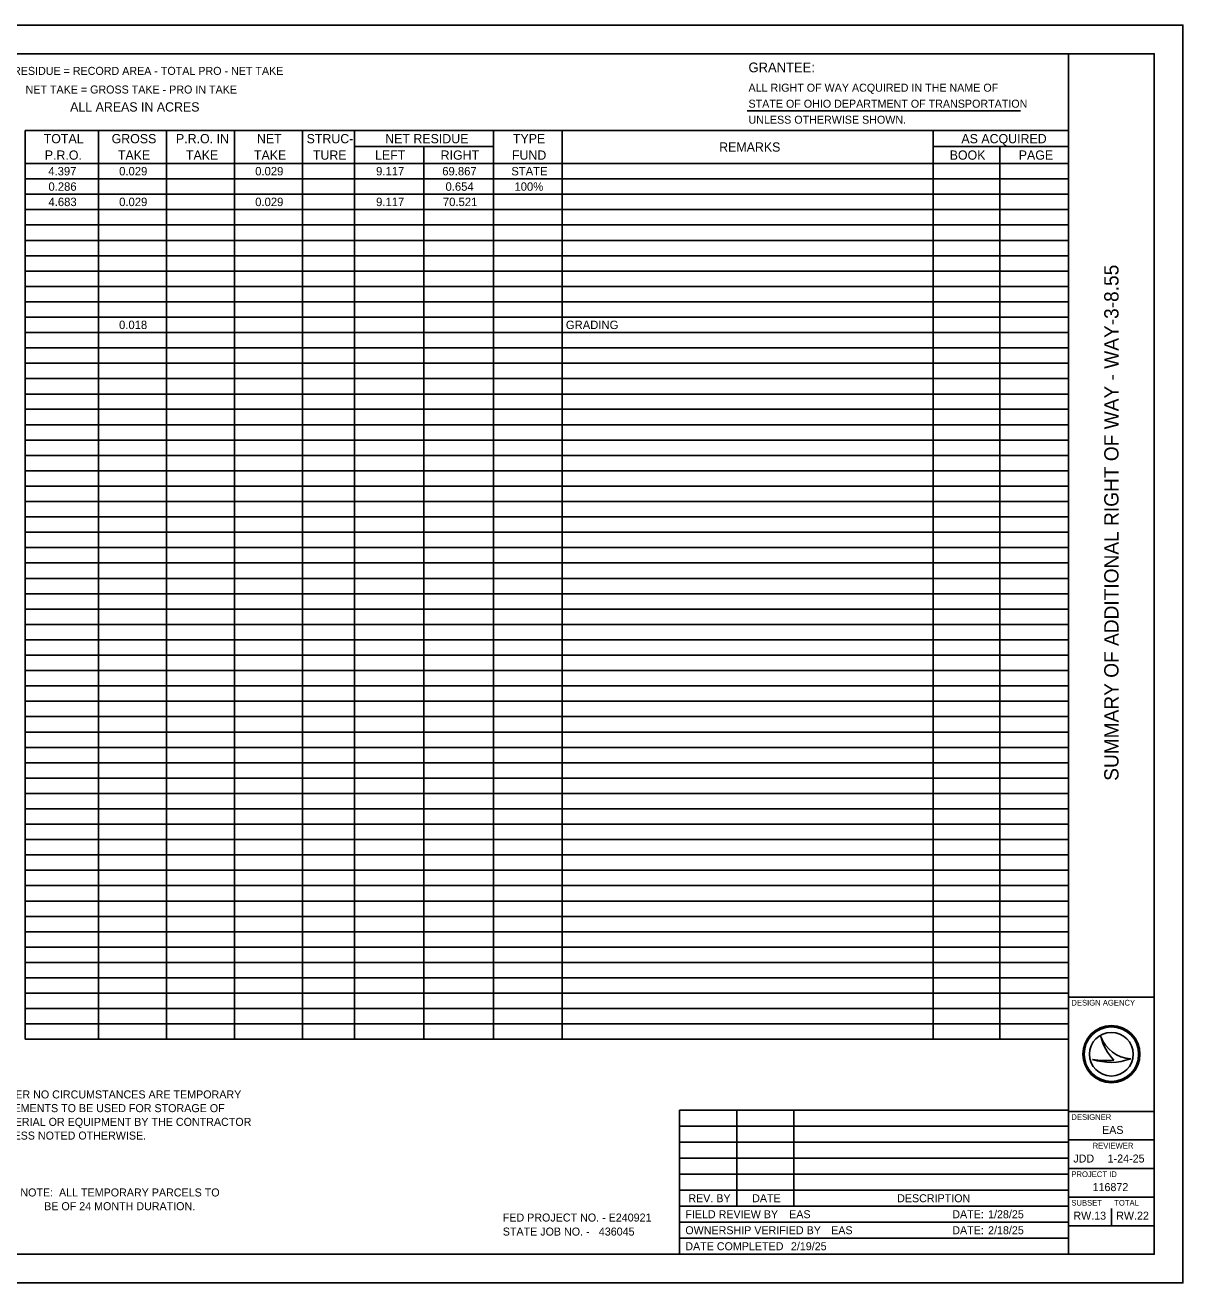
# Model space of a CAD drawing. Extents: x 0 to 34, y 0 to 22.
# Drawn here: x 13.75 to 34, y 0 to 22 of the extents above; entities that cross this region are included whole.
import ezdxf

# ---------------------------------------------------------------- set-up
doc = ezdxf.new("R2010")
doc.units = 0
for name, color, linetype in [('SH_Border', 7, 'Continuous'), ('SH_Cut_Line', 7, 'Continuous'), ('SH_Data', 7, 'Continuous'), ('SH_Text', 7, 'Continuous')]:
    doc.layers.add(name, color=color, linetype=linetype)

msp = doc.modelspace()

# ---------------------------------------------------------------- linework, layer by layer
at = {"layer": 'SH_Border'}
for p, q in [((32, 0.5), (32, 21.5)), ((32, 5), (33.5, 5)), ((32, 3), (33.5, 3)), ((32, 2.5), (33.5, 2.5)), ((32, 2), (33.5, 2)), ((32, 1.5), (33.5, 1.5)), ((32, 1), (33.5, 1))]:
    msp.add_line(p, q, dxfattribs=at)
msp.add_lwpolyline([(1.5, 21.5), (33.5, 21.5), (33.5, 0.5), (1.5, 0.5)], close=True, dxfattribs=at)
at = {"layer": 'SH_Cut_Line'}
msp.add_lwpolyline([(0, 0), (34, 0), (34, 22), (0, 22)], close=True, dxfattribs=at)
at = {"layer": 'SH_Data'}
for p, q in [((32.567, 4.31), (32.567, 4.31)), ((32.75, 4), (32.75, 4)), ((32.417, 3.91), (32.417, 3.91)), ((33.087, 3.919), (33.087, 3.919)), ((32.75, 1), (32.75, 1.3))]:
    msp.add_line(p, q, dxfattribs=at)
for radius in [0.5, 0.477, 0.477, 0.382]:
    msp.add_circle((32.75, 4), radius, dxfattribs=at)
for centre, radius, start, end in [((33.116, 4.498), 0.58, 198.9257, 198.9319), ((33.347, 4.47), 0.796, 191.6379, 191.6421), ((33.116, 4.498), 0.58, 198.9319, 267.1657), ((33.347, 4.47), 0.796, 191.6421, 226.0947), ((32.739, 4.87), 1.013, 251.4576, 290.0832), ((32.648, 5.154), 1.266, 259.4964, 259.4995), ((32.739, 4.87), 1.013, 251.4527, 251.4576), ((32.648, 5.154), 1.266, 259.4995, 276.6672)]:
    msp.add_arc(centre, radius, start, end, dxfattribs=at)
at = {"layer": 'SH_Text'}
for p, q in [((26.38, 20.499), (31.16, 20.499)), ((13.749, 20.156), (16.219, 20.156)), ((13.749, 20.156), (13.749, 15.817)), ((15.029, 20.156), (15.029, 15.817)), ((16.219, 20.156), (30.797, 20.156)), ((16.219, 20.156), (16.219, 15.817)), ((17.409, 20.156), (17.409, 15.817)), ((18.599, 20.156), (18.599, 15.817)), ((19.508, 20.156), (19.508, 15.817)), ((21.94, 20.156), (21.94, 15.817)), ((23.143, 20.156), (23.143, 15.817)), ((29.632, 20.156), (29.632, 15.817)), ((30.797, 20.156), (32, 20.156)), ((32, 20.156), (32, 15.817)), ((19.508, 19.875), (21.94, 19.875)), ((20.724, 19.875), (20.724, 15.817)), ((29.632, 19.875), (30.797, 19.875)), ((30.797, 19.875), (32, 19.875)), ((30.797, 19.875), (30.797, 15.817)), ((13.749, 19.58), (16.219, 19.58)), ((16.219, 19.58), (30.797, 19.58)), ((30.797, 19.58), (32, 19.58)), ((13.749, 19.311), (16.219, 19.311)), ((16.219, 19.311), (30.797, 19.311)), ((30.797, 19.311), (32, 19.311)), ((13.749, 19.043), (16.219, 19.043)), ((16.219, 19.043), (23.143, 19.043)), ((23.143, 19.043), (30.797, 19.043)), ((30.797, 19.043), (32, 19.043)), ((13.749, 18.774), (16.219, 18.774)), ((16.219, 18.774), (30.797, 18.774)), ((30.797, 18.774), (32, 18.774)), ((13.749, 18.505), (16.219, 18.505)), ((16.219, 18.505), (30.797, 18.505)), ((30.797, 18.505), (32, 18.505)), ((13.749, 18.236), (16.219, 18.236)), ((16.219, 18.236), (30.797, 18.236)), ((30.797, 18.236), (32, 18.236)), ((13.749, 17.967), (16.219, 17.967)), ((16.219, 17.967), (30.797, 17.967)), ((30.797, 17.967), (32, 17.967)), ((13.749, 17.699), (16.219, 17.699)), ((16.219, 17.699), (30.797, 17.699)), ((30.797, 17.699), (32, 17.699)), ((13.749, 17.43), (16.219, 17.43)), ((16.219, 17.43), (30.797, 17.43)), ((30.797, 17.43), (32, 17.43)), ((13.749, 17.161), (16.219, 17.161)), ((16.219, 17.161), (30.797, 17.161)), ((30.797, 17.161), (32, 17.161)), ((13.749, 16.892), (16.219, 16.892)), ((16.219, 16.892), (30.797, 16.892)), ((30.797, 16.892), (32, 16.892)), ((13.749, 16.624), (16.219, 16.624)), ((16.219, 16.624), (30.797, 16.624)), ((30.797, 16.624), (32, 16.624)), ((13.749, 16.355), (16.219, 16.355)), ((16.219, 16.355), (30.797, 16.355)), ((30.797, 16.355), (32, 16.355)), ((13.749, 16.086), (16.219, 16.086)), ((16.219, 16.086), (30.797, 16.086)), ((30.797, 16.086), (32, 16.086)), ((13.749, 15.817), (16.219, 15.817)), ((13.749, 15.817), (13.749, 15.548)), ((15.029, 15.817), (15.029, 15.548)), ((16.219, 15.817), (30.797, 15.817)), ((16.219, 15.817), (16.219, 15.548)), ((17.409, 15.817), (17.409, 15.548)), ((18.599, 15.817), (18.599, 15.548)), ((19.508, 15.817), (19.508, 15.548)), ((20.724, 15.817), (20.724, 15.548)), ((21.94, 15.817), (21.94, 15.548)), ((23.143, 15.817), (23.143, 15.548)), ((29.632, 15.817), (29.632, 15.548)), ((30.797, 15.817), (32, 15.817)), ((30.797, 15.817), (30.797, 15.548)), ((32, 15.817), (32, 15.548)), ((13.749, 15.548), (16.219, 15.548)), ((13.749, 15.548), (13.749, 15.28)), ((15.029, 15.548), (15.029, 15.28)), ((16.219, 15.548), (30.797, 15.548)), ((16.219, 15.548), (16.219, 15.28)), ((17.409, 15.548), (17.409, 15.28)), ((18.599, 15.548), (18.599, 15.28)), ((19.508, 15.548), (19.508, 15.28)), ((20.724, 15.548), (20.724, 15.28)), ((21.94, 15.548), (21.94, 15.28)), ((23.143, 15.548), (23.143, 15.28)), ((29.632, 15.548), (29.632, 15.28)), ((30.797, 15.548), (32, 15.548)), ((30.797, 15.548), (30.797, 15.28)), ((32, 15.548), (32, 15.28)), ((13.749, 15.28), (16.219, 15.28)), ((13.749, 15.28), (13.749, 15.011)), ((15.029, 15.28), (15.029, 15.011)), ((16.219, 15.28), (30.797, 15.28)), ((16.219, 15.28), (16.219, 15.011)), ((17.409, 15.28), (17.409, 15.011)), ((18.599, 15.28), (18.599, 15.011)), ((19.508, 15.28), (19.508, 15.011)), ((20.724, 15.28), (20.724, 15.011)), ((21.94, 15.28), (21.94, 15.011)), ((23.143, 15.28), (23.143, 15.011)), ((29.632, 15.28), (29.632, 15.011)), ((30.797, 15.28), (32, 15.28)), ((30.797, 15.28), (30.797, 15.011)), ((32, 15.28), (32, 15.011)), ((13.749, 15.011), (16.219, 15.011)), ((13.749, 15.011), (13.749, 14.473)), ((15.029, 15.011), (15.029, 14.473)), ((16.219, 15.011), (30.797, 15.011)), ((16.219, 15.011), (16.219, 14.473)), ((17.409, 15.011), (17.409, 14.473)), ((18.599, 15.011), (18.599, 14.473)), ((19.508, 15.011), (19.508, 14.473)), ((20.724, 15.011), (20.724, 14.473)), ((21.94, 15.011), (21.94, 14.473)), ((23.143, 15.011), (23.143, 14.473)), ((29.632, 15.011), (29.632, 14.473)), ((30.797, 15.011), (32, 15.011)), ((30.797, 15.011), (30.797, 14.473)), ((32, 15.011), (32, 14.473)), ((13.749, 14.742), (16.219, 14.742)), ((16.219, 14.742), (30.797, 14.742)), ((30.797, 14.742), (32, 14.742)), ((13.749, 14.473), (16.219, 14.473)), ((13.749, 14.473), (13.749, 14.205)), ((15.029, 14.473), (15.029, 14.205)), ((16.219, 14.473), (30.797, 14.473)), ((16.219, 14.473), (16.219, 14.205)), ((17.409, 14.473), (17.409, 14.205)), ((18.599, 14.473), (18.599, 14.205)), ((19.508, 14.473), (19.508, 14.205)), ((20.724, 14.473), (20.724, 14.205)), ((21.94, 14.473), (21.94, 14.205)), ((23.143, 14.473), (23.143, 14.205)), ((29.632, 14.473), (29.632, 14.205)), ((30.797, 14.473), (32, 14.473)), ((30.797, 14.473), (30.797, 14.205)), ((32, 14.473), (32, 14.205)), ((13.749, 14.205), (16.219, 14.205)), ((13.749, 14.205), (13.749, 9.635)), ((15.029, 14.205), (15.029, 9.635)), ((16.219, 14.205), (30.797, 14.205)), ((16.219, 14.205), (16.219, 9.635)), ((17.409, 14.205), (17.409, 9.635)), ((18.599, 14.205), (18.599, 9.635)), ((19.508, 14.205), (19.508, 9.635)), ((20.724, 14.205), (20.724, 9.635)), ((21.94, 14.205), (21.94, 9.635)), ((23.143, 14.205), (23.143, 9.635)), ((29.632, 14.205), (29.632, 9.635)), ((30.797, 14.205), (32, 14.205)), ((30.797, 14.205), (30.797, 9.635)), ((32, 14.205), (32, 9.635)), ((13.749, 13.936), (16.219, 13.936)), ((16.219, 13.936), (30.797, 13.936)), ((30.797, 13.936), (32, 13.936)), ((13.749, 13.667), (16.219, 13.667)), ((16.219, 13.667), (30.797, 13.667)), ((30.797, 13.667), (32, 13.667)), ((13.749, 13.398), (16.219, 13.398)), ((16.219, 13.398), (30.797, 13.398)), ((30.797, 13.398), (32, 13.398)), ((13.749, 13.129), (16.219, 13.129)), ((16.219, 13.129), (30.797, 13.129)), ((30.797, 13.129), (32, 13.129)), ((13.749, 12.861), (16.219, 12.861)), ((16.219, 12.861), (30.797, 12.861)), ((30.797, 12.861), (32, 12.861)), ((13.749, 12.592), (16.219, 12.592)), ((16.219, 12.592), (30.797, 12.592)), ((30.797, 12.592), (32, 12.592)), ((13.749, 12.323), (16.219, 12.323)), ((16.219, 12.323), (30.797, 12.323)), ((30.797, 12.323), (32, 12.323)), ((13.749, 12.054), (16.219, 12.054)), ((16.219, 12.054), (30.797, 12.054)), ((30.797, 12.054), (32, 12.054)), ((13.749, 11.786), (16.219, 11.786)), ((16.219, 11.786), (30.797, 11.786)), ((30.797, 11.786), (32, 11.786)), ((13.749, 11.517), (16.219, 11.517)), ((16.219, 11.517), (30.797, 11.517)), ((30.797, 11.517), (32, 11.517)), ((13.749, 11.248), (16.219, 11.248)), ((16.219, 11.248), (30.797, 11.248)), ((30.797, 11.248), (32, 11.248)), ((13.749, 10.979), (16.219, 10.979)), ((16.219, 10.979), (30.797, 10.979)), ((30.797, 10.979), (32, 10.979)), ((13.749, 10.71), (16.219, 10.71)), ((16.219, 10.71), (30.797, 10.71)), ((30.797, 10.71), (32, 10.71)), ((13.749, 10.442), (16.219, 10.442)), ((16.219, 10.442), (30.797, 10.442)), ((30.797, 10.442), (32, 10.442)), ((13.749, 10.173), (16.219, 10.173)), ((16.219, 10.173), (30.797, 10.173)), ((30.797, 10.173), (32, 10.173)), ((13.749, 9.904), (16.219, 9.904)), ((16.219, 9.904), (30.797, 9.904)), ((30.797, 9.904), (32, 9.904)), ((13.749, 9.635), (16.219, 9.635)), ((13.749, 9.635), (13.749, 9.367)), ((15.029, 9.635), (15.029, 9.367)), ((16.219, 9.635), (30.797, 9.635)), ((16.219, 9.635), (16.219, 9.367)), ((17.409, 9.635), (17.409, 9.367)), ((18.599, 9.635), (18.599, 9.367)), ((19.508, 9.635), (19.508, 9.367)), ((20.724, 9.635), (20.724, 9.367)), ((21.94, 9.635), (21.94, 9.367)), ((23.143, 9.635), (23.143, 9.367)), ((29.632, 9.635), (29.632, 9.367)), ((30.797, 9.635), (32, 9.635)), ((30.797, 9.635), (30.797, 9.367)), ((32, 9.635), (32, 9.367)), ((13.749, 9.367), (16.219, 9.367)), ((13.749, 9.367), (13.749, 9.098)), ((15.029, 9.367), (15.029, 9.098)), ((16.219, 9.367), (30.797, 9.367)), ((16.219, 9.367), (16.219, 9.098)), ((17.409, 9.367), (17.409, 9.098)), ((18.599, 9.367), (18.599, 9.098)), ((19.508, 9.367), (19.508, 9.098)), ((20.724, 9.367), (20.724, 9.098)), ((21.94, 9.367), (21.94, 9.098)), ((23.143, 9.367), (23.143, 9.098)), ((29.632, 9.367), (29.632, 9.098)), ((30.797, 9.367), (32, 9.367)), ((30.797, 9.367), (30.797, 9.098)), ((32, 9.367), (32, 9.098)), ((13.749, 9.098), (16.219, 9.098)), ((13.749, 9.098), (13.749, 8.291)), ((15.029, 9.098), (15.029, 8.291)), ((16.219, 9.098), (30.797, 9.098)), ((16.219, 9.098), (16.219, 8.291)), ((17.409, 9.098), (17.409, 8.291)), ((18.599, 9.098), (18.599, 8.291)), ((19.508, 9.098), (19.508, 8.291)), ((20.724, 9.098), (20.724, 8.291)), ((21.94, 9.098), (21.94, 8.291)), ((23.143, 9.098), (23.143, 8.291)), ((29.632, 9.098), (29.632, 8.291)), ((30.797, 9.098), (32, 9.098)), ((30.797, 9.098), (30.797, 8.291)), ((32, 9.098), (32, 8.291)), ((13.749, 8.829), (16.219, 8.829)), ((16.219, 8.829), (30.797, 8.829)), ((30.797, 8.829), (32, 8.829)), ((13.749, 8.56), (16.219, 8.56)), ((16.219, 8.56), (30.797, 8.56)), ((30.797, 8.56), (32, 8.56)), ((13.749, 8.291), (16.219, 8.291)), ((13.749, 8.291), (13.749, 8.023)), ((15.029, 8.291), (15.029, 8.023)), ((16.219, 8.291), (30.797, 8.291)), ((16.219, 8.291), (16.219, 8.023)), ((17.409, 8.291), (17.409, 8.023)), ((18.599, 8.291), (18.599, 8.023)), ((19.508, 8.291), (19.508, 8.023)), ((20.724, 8.291), (20.724, 8.023)), ((21.94, 8.291), (21.94, 8.023)), ((23.143, 8.291), (23.143, 8.023)), ((29.632, 8.291), (29.632, 8.023)), ((30.797, 8.291), (32, 8.291)), ((30.797, 8.291), (30.797, 8.023)), ((32, 8.291), (32, 8.023)), ((13.749, 8.023), (16.219, 8.023)), ((13.749, 8.023), (13.749, 7.754)), ((15.029, 8.023), (15.029, 7.754)), ((16.219, 8.023), (30.797, 8.023)), ((16.219, 8.023), (16.219, 7.754)), ((17.409, 8.023), (17.409, 7.754)), ((18.599, 8.023), (18.599, 7.754)), ((19.508, 8.023), (19.508, 7.754)), ((20.724, 8.023), (20.724, 7.754)), ((21.94, 8.023), (21.94, 7.754)), ((23.143, 8.023), (23.143, 7.754)), ((29.632, 8.023), (29.632, 7.754)), ((30.797, 8.023), (32, 8.023)), ((30.797, 8.023), (30.797, 7.754)), ((32, 8.023), (32, 7.754)), ((13.749, 7.754), (16.219, 7.754)), ((13.749, 7.754), (13.749, 6.948)), ((15.029, 7.754), (15.029, 6.948)), ((16.219, 7.754), (30.797, 7.754)), ((16.219, 7.754), (16.219, 6.948)), ((17.409, 7.754), (17.409, 6.948)), ((18.599, 7.754), (18.599, 6.948)), ((19.508, 7.754), (19.508, 6.948)), ((20.724, 7.754), (20.724, 6.948)), ((21.94, 7.754), (21.94, 6.948)), ((23.143, 7.754), (23.143, 6.948)), ((29.632, 7.754), (29.632, 6.948)), ((30.797, 7.754), (32, 7.754)), ((30.797, 7.754), (30.797, 6.948)), ((32, 7.754), (32, 6.948)), ((13.749, 7.485), (16.219, 7.485)), ((16.219, 7.485), (30.797, 7.485)), ((30.797, 7.485), (32, 7.485)), ((13.749, 7.216), (16.219, 7.216)), ((16.219, 7.216), (30.797, 7.216)), ((30.797, 7.216), (32, 7.216)), ((13.749, 6.948), (16.219, 6.948)), ((13.749, 6.948), (13.749, 6.679)), ((15.029, 6.948), (15.029, 6.679)), ((16.219, 6.948), (30.797, 6.948)), ((16.219, 6.948), (16.219, 6.679)), ((17.409, 6.948), (17.409, 6.679)), ((18.599, 6.948), (18.599, 6.679)), ((19.508, 6.948), (19.508, 6.679)), ((20.724, 6.948), (20.724, 6.679)), ((21.94, 6.948), (21.94, 6.679)), ((23.143, 6.948), (23.143, 6.679)), ((29.632, 6.948), (29.632, 6.679)), ((30.797, 6.948), (32, 6.948)), ((30.797, 6.948), (30.797, 6.679)), ((32, 6.948), (32, 6.679)), ((13.749, 6.679), (16.219, 6.679)), ((13.749, 6.679), (13.749, 4.26)), ((15.029, 6.679), (15.029, 4.26)), ((16.219, 6.679), (30.797, 6.679)), ((16.219, 6.679), (16.219, 4.26)), ((17.409, 6.679), (17.409, 4.26)), ((18.599, 6.679), (18.599, 4.26)), ((19.508, 6.679), (19.508, 4.26)), ((20.724, 6.679), (20.724, 4.26)), ((21.94, 6.679), (21.94, 4.26)), ((23.143, 6.679), (23.143, 4.26)), ((29.632, 6.679), (29.632, 4.26)), ((30.797, 6.679), (32, 6.679)), ((30.797, 6.679), (30.797, 4.26)), ((32, 6.679), (32, 4.26)), ((13.749, 6.41), (16.219, 6.41)), ((16.219, 6.41), (30.797, 6.41)), ((30.797, 6.41), (32, 6.41)), ((13.749, 6.141), (16.219, 6.141)), ((16.219, 6.141), (30.797, 6.141)), ((30.797, 6.141), (32, 6.141)), ((13.749, 5.872), (16.219, 5.872)), ((16.219, 5.872), (30.797, 5.872)), ((30.797, 5.872), (32, 5.872)), ((13.749, 5.604), (16.219, 5.604)), ((16.219, 5.604), (30.797, 5.604)), ((30.797, 5.604), (32, 5.604)), ((13.749, 5.335), (16.219, 5.335)), ((16.219, 5.335), (30.797, 5.335)), ((30.797, 5.335), (32, 5.335)), ((13.749, 5.066), (16.219, 5.066)), ((16.219, 5.066), (30.797, 5.066)), ((30.797, 5.066), (32, 5.066)), ((13.749, 4.797), (16.219, 4.797)), ((16.219, 4.797), (30.797, 4.797)), ((30.797, 4.797), (32, 4.797)), ((13.749, 4.529), (16.219, 4.529)), ((16.219, 4.529), (30.797, 4.529)), ((30.797, 4.529), (32, 4.529)), ((13.749, 4.26), (16.219, 4.26)), ((16.219, 4.26), (30.797, 4.26)), ((30.797, 4.26), (32, 4.26)), ((25.197, 3.02), (25.197, 0.5)), ((25.197, 3.02), (32, 3.02)), ((26.197, 3.02), (26.197, 1.34)), ((27.197, 3.02), (27.197, 1.34)), ((25.197, 2.74), (32, 2.74)), ((25.197, 2.46), (32, 2.46)), ((25.197, 2.18), (32, 2.18)), ((25.197, 1.9), (32, 1.9)), ((25.197, 1.62), (32, 1.62)), ((25.197, 1.34), (32, 1.34)), ((25.197, 1.06), (32, 1.06)), ((25.197, 0.78), (32, 0.78)), ((32, 0.5), (32, 0.5))]:
    msp.add_line(p, q, dxfattribs=at)

# ---------------------------------------------------------------- texts
at = {"layer": 'SH_Data'}
msp.add_text('SUMMARY OF ADDITIONAL RIGHT OF WAY - WAY-3-8.55', height=0.25, rotation=90, dxfattribs=at).set_placement((32.875, 8.782))
for s, height, p in [('DESIGN AGENCY', 0.1, (32.05, 4.85)), ('DESIGNER', 0.1, (32.05, 2.85)), ('EAS', 0.14, (32.587, 2.605)), ('REVIEWER', 0.1, (32.422, 2.35)), ('JDD', 0.14, (32.084, 2.105)), ('1-24-25', 0.14, (32.685, 2.105)), ('PROJECT ID', 0.1, (32.05, 1.85)), ('SUBSET', 0.1, (32.05, 1.35)), ('TOTAL', 0.1, (32.8, 1.35)), ('RW.13', 0.14, (32.085, 1.105)), ('RW.22', 0.14, (32.834, 1.105))]:
    msp.add_text(s, height=height, dxfattribs=at).set_placement(p)
at = {"layer": 'SH_Text'}
for s, height, p in [('GRANTEE:', 0.17, (26.402, 21.176)), ('NET RESIDUE = RECORD AREA - TOTAL PRO - NET TAKE', 0.14, (13.111, 21.13)), ('NET TAKE = GROSS TAKE - PRO IN TAKE', 0.14, (13.756, 20.804)), ('ALL RIGHT OF WAY ACQUIRED IN THE NAME OF', 0.14, (26.402, 20.836)), ('STATE OF OHIO DEPARTMENT OF TRANSPORTATION     ', 0.14, (26.402, 20.556)), ('ALL AREAS IN ACRES', 0.16191, (14.536, 20.489)), ('UNLESS OTHERWISE SHOWN.', 0.14, (26.402, 20.276)), ('TOTAL', 0.1619, (14.073, 19.934)), ('GROSS', 0.1619, (15.261, 19.934)), ('P.R.O. IN', 0.1619, (16.387, 19.934)), ('NET', 0.1619, (17.803, 19.934)), ('STRUC-', 0.1619, (18.672, 19.934)), ('NET RESIDUE', 0.16191, (20.047, 19.934)), ('TYPE', 0.1619, (22.281, 19.934)), ('AS ACQUIRED', 0.16191, (30.126, 19.934)), ('P.R.O.', 0.1619, (14.092, 19.646)), ('TAKE', 0.1619, (15.371, 19.646)), ('TAKE', 0.1619, (16.561, 19.646)), ('TAKE', 0.1619, (17.751, 19.646)), ('TURE', 0.1619, (18.782, 19.646)), ('LEFT', 0.1619, (19.869, 19.646)), ('RIGHT', 0.1619, (21.017, 19.646)), ('FUND', 0.1619, (22.264, 19.646)), ('REMARKS', 0.1619, (25.889, 19.787)), ('BOOK', 0.1619, (29.921, 19.646)), ('PAGE', 0.1619, (31.129, 19.646)), ('4.397', 0.1472, (14.153, 19.372)), ('0.029', 0.1472, (15.393, 19.372)), ('0.029', 0.1472, (17.773, 19.372)), ('9.117', 0.1472, (19.888, 19.372)), ('69.867', 0.1472, (21.045, 19.372)), ('STATE', 0.1472, (22.253, 19.372)), ('0.286', 0.1472, (14.156, 19.103)), ('0.654', 0.1472, (21.102, 19.103)), ('100%', 0.1472, (22.308, 19.103)), ('4.683', 0.1472, (14.157, 18.835)), ('0.029', 0.1472, (15.393, 18.835)), ('0.029', 0.1472, (17.773, 18.835)), ('9.117', 0.1472, (19.888, 18.835)), ('70.521', 0.1472, (21.056, 18.835)), ('0.018', 0.1472, (15.391, 16.684)), ('GRADING', 0.1472, (23.207, 16.684)), ('UNDER NO CIRCUMSTANCES ARE TEMPORARY', 0.14, (13.171, 3.226)), ('EASEMENTS TO BE USED FOR STORAGE OF', 0.14, (13.171, 2.986)), ('MATERIAL OR EQUIPMENT BY THE CONTRACTOR', 0.14, (13.171, 2.746)), ('UNLESS NOTED OTHERWISE.', 0.14, (13.171, 2.506)), ('NOTE:  ALL TEMPORARY PARCELS TO', 0.14, (13.665, 1.511)), ('REV. BY', 0.14, (25.35, 1.41)), ('DATE', 0.14, (26.466, 1.41)), ('DESCRIPTION', 0.14, (29.002, 1.41)), ('116872', 0.14, (32.421, 1.605)), ('        BE OF 24 MONTH DURATION.', 0.14, (13.665, 1.271)), ('FED PROJECT NO. - E240921', 0.14, (22.104, 1.072)), ('FIELD REVIEW BY', 0.14, (25.297, 1.13)), ('EAS                      ', 0.14, (27.113, 1.13)), ('DATE:', 0.14, (29.967, 1.13)), ('1/28/25 ', 0.14, (30.593, 1.13)), ('STATE JOB NO. -', 0.14, (22.104, 0.827)), ('436045', 0.14, (23.784, 0.827)), ('OWNERSHIP VERIFIED BY', 0.14, (25.297, 0.85)), ('EAS               ', 0.14, (27.848, 0.85)), ('DATE:', 0.14, (29.967, 0.85)), ('2/18/25 ', 0.14, (30.593, 0.85)), ('DATE COMPLETED', 0.14, (25.297, 0.57)), ('2/19/25                             ', 0.14, (27.144, 0.57))]:
    msp.add_text(s, height=height, dxfattribs=at).set_placement(p)

doc.saveas('drawing.dxf')
